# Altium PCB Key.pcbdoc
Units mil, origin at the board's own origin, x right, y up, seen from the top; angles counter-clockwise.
Board outline 1714.59 x 1483.35 mil, 2 copper layers (Top Layer, Bottom Layer); 3 components, 7 nets, 8 pads, 0 vias.
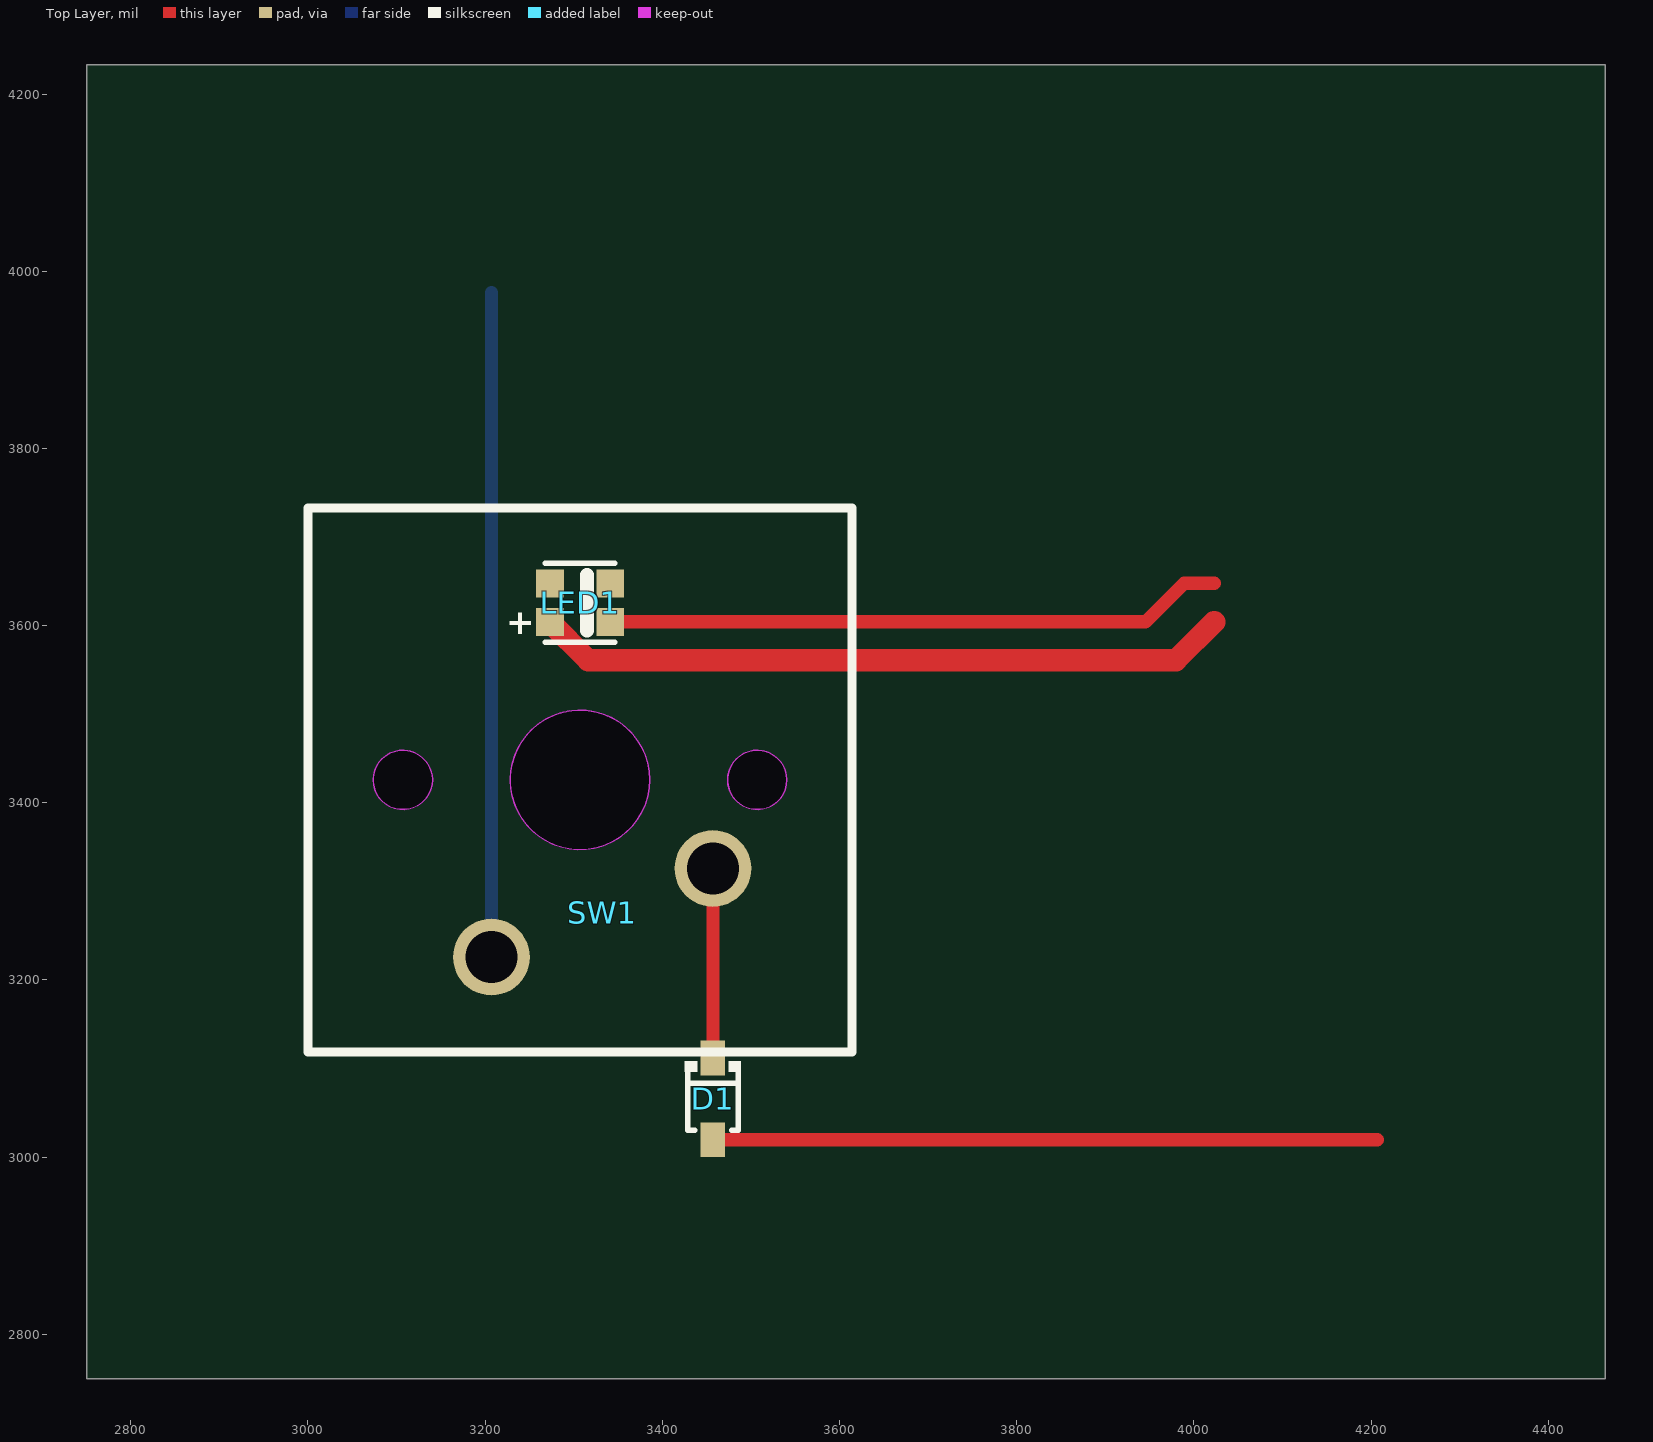
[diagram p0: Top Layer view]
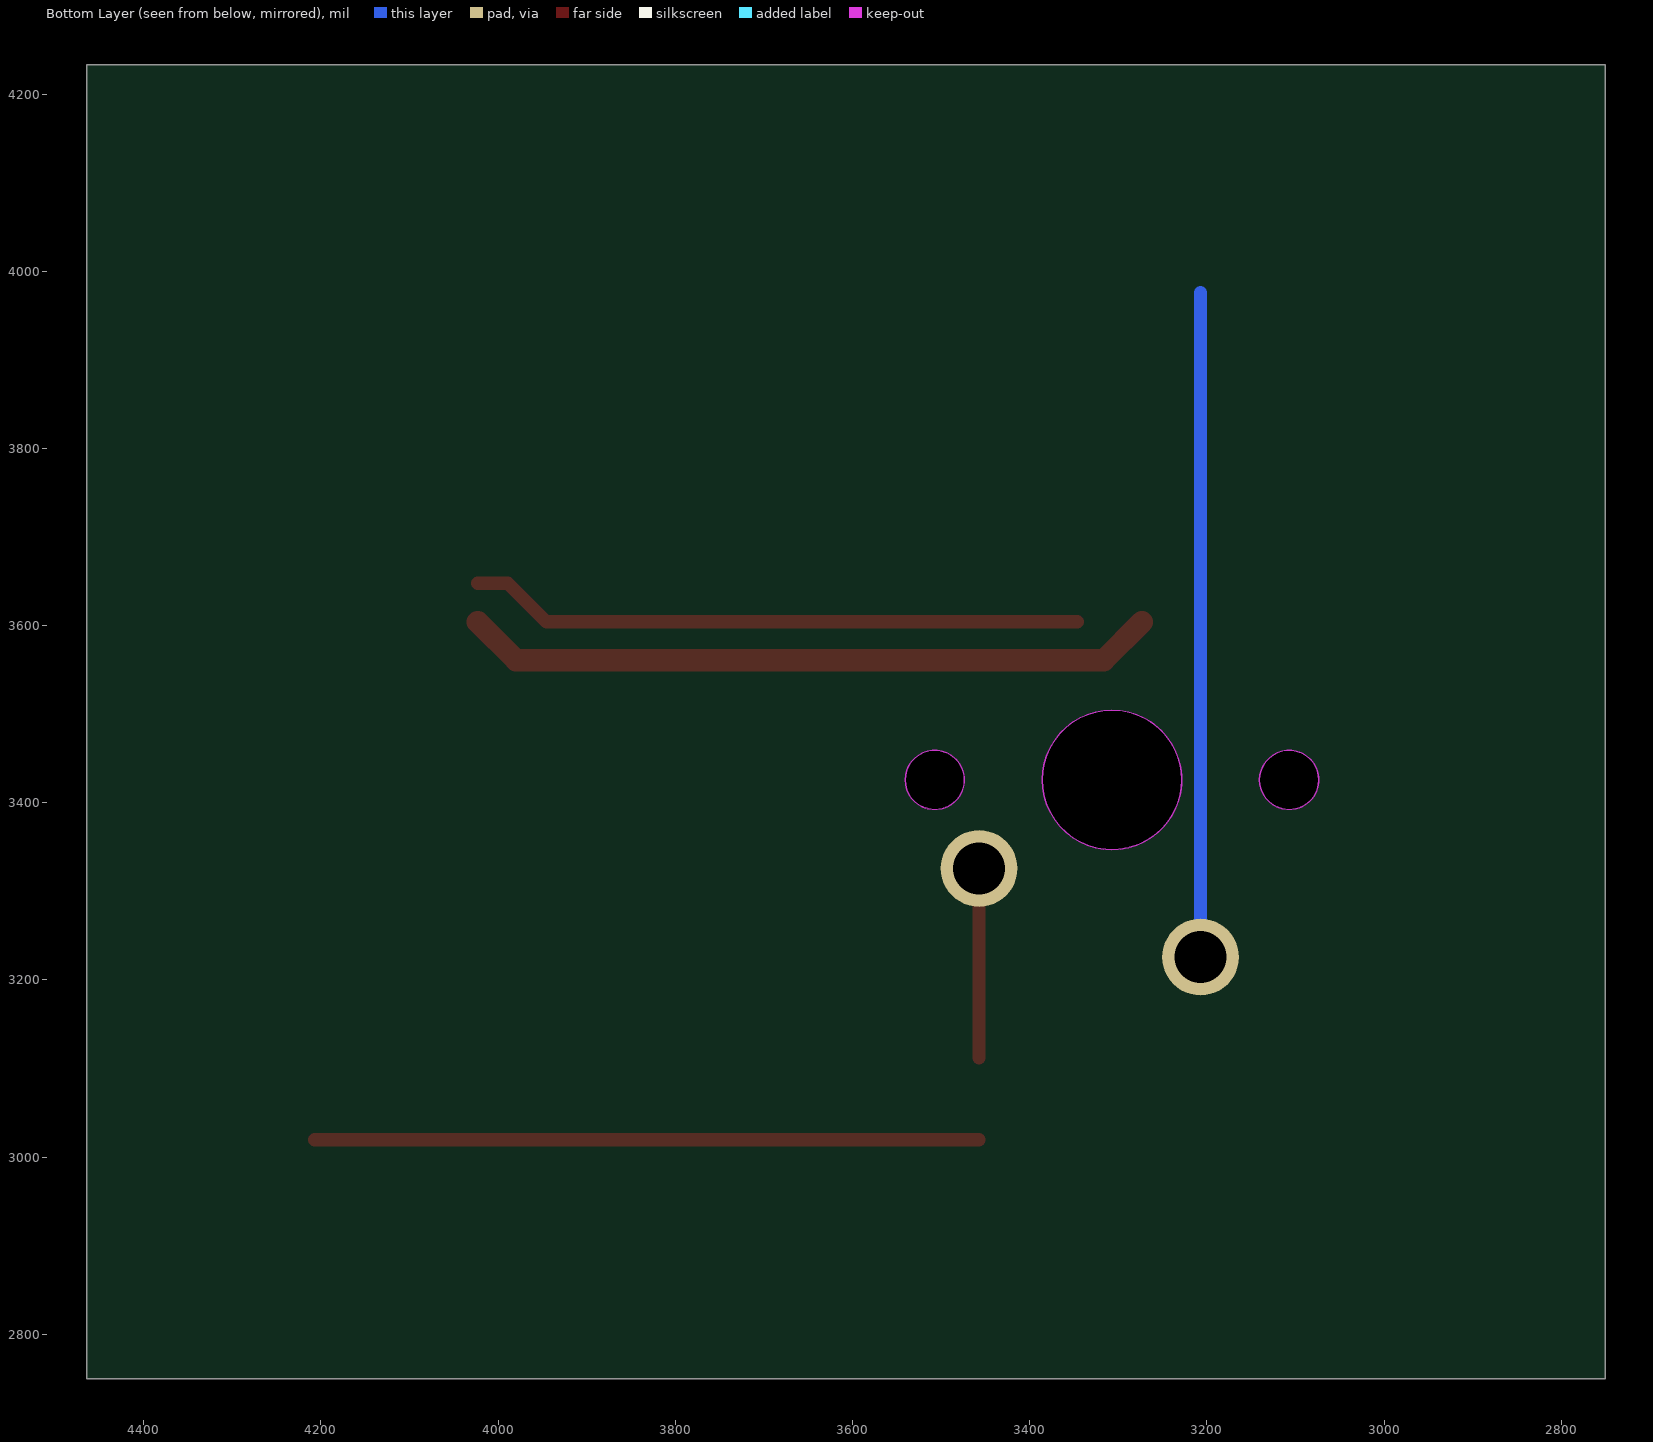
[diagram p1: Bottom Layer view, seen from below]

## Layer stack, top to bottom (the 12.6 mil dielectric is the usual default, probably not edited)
Top Layer: signal copper (thickness not stored)
Dielectric: dielectric 12.6, FR-4, Dk 4.8
Bottom Layer: signal copper (thickness not stored)

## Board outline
4464.59,2750 2750,2750 2750,4233.35 4464.59,4233.35

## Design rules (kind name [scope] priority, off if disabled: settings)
BoardOutlineClearance copperThickness1oz [All] p0: genericclearance=10 ignorepadtopadclearanceinfootprint=FALSE except(0: Arc-SplitContinuation Track-SplitContinuation SMDPad-SplitContinuation THPad-SplitContinuation Via-SplitContinuation Fill-SplitContinuation Poly-SplitContinuation Region-SplitContinuation Text-SplitContinuation; 6: Track-CutoutEdge SMDPad-CutoutEdge THPad-CutoutEdge Via-CutoutEdge Region-CutoutEdge; 11.8: Track-OutlineEdge SMDPad-OutlineEdge THPad-OutlineEdge Via-OutlineEdge Fill-OutlineEdge Region-OutlineEdge Poly-OutlineEdge Text-OutlineEdge Fill-CutoutEdge)
BoardOutlineClearance copperThickness2oz [All] p0: genericclearance=10 ignorepadtopadclearanceinfootprint=FALSE except(0: Arc-SplitContinuation Track-SplitContinuation SMDPad-SplitContinuation THPad-SplitContinuation Via-SplitContinuation Fill-SplitContinuation Poly-SplitContinuation Region-SplitContinuation Text-SplitContinuation; 6: Track-CutoutEdge SMDPad-CutoutEdge THPad-CutoutEdge Via-CutoutEdge Region-CutoutEdge; 11.8: Track-OutlineEdge SMDPad-OutlineEdge THPad-OutlineEdge Via-OutlineEdge Fill-OutlineEdge Region-OutlineEdge Poly-OutlineEdge Text-OutlineEdge Fill-CutoutEdge)
Clearance copperThickness1oz [(InNet('GND') OR InNet('VCC') OR InNet('COL') OR InNet('DI') OR InNet('DO') OR InNet('ROW') OR InNet('$1N2306'))] p1: gap=7 ignorepadtopadclearanceinfootprint=FALSE except(4: Track-Track; 6: Track-SMDPad SMDPad-SMDPad Track-THPad SMDPad-THPad THPad-THPad Track-Via SMDPad-Via THPad-Via Via-Via SMDPad-Fill THPad-Fill Via-Fill Fill-Fill Track-Region SMDPad-Region THPad-Region Via-Region Region-Region Track-Poly SMDPad-Poly THPad-Poly Via-Poly Fill-Poly Region-Poly Poly-Poly Track-Text SMDPad-Text THPad-Text Via-Text Fill-Text Region-Text Poly-Text Text-Text; 6.9: Track-Hole SMDPad-Hole THPad-Hole Via-Hole Fill-Hole Region-Hole Poly-Hole Text-Hole Sheet-Hole; 11.8: Track-Fill Fill-Region Track-Sheet SMDPad-Sheet THPad-Sheet Via-Sheet Fill-Sheet Region-Sheet Poly-Sheet Text-Sheet)
Clearance copperThickness2oz [All] p1: gap=7 ignorepadtopadclearanceinfootprint=FALSE except(6: Track-SMDPad SMDPad-SMDPad Track-THPad SMDPad-THPad THPad-THPad Track-Via SMDPad-Via THPad-Via Via-Via SMDPad-Fill THPad-Fill Via-Fill Fill-Fill Track-Region SMDPad-Region THPad-Region Via-Region Region-Region Track-Poly SMDPad-Poly THPad-Poly Via-Poly Fill-Poly Region-Poly Poly-Poly Track-Text SMDPad-Text THPad-Text Via-Text Fill-Text Region-Text Poly-Text Text-Text; 6.9: Track-Hole SMDPad-Hole THPad-Hole Via-Hole Fill-Hole Region-Hole Poly-Hole Text-Hole Sheet-Hole; 8: Track-Track; 11.8: Track-Fill Fill-Region Track-Sheet SMDPad-Sheet THPad-Sheet Via-Sheet Fill-Sheet Region-Sheet Poly-Sheet Text-Sheet)
DiffPairsRouting differentialPair [All] p1: maxuncoupledlength=10 minlimit=6 maxlimit=6 mostfreqgap=6 toplayer_minwidth=5 toplayer_prefwidth=10 toplayer_maxwidth=100 bottomlayer_minwidth=5 bottomlayer_prefwidth=10 bottomlayer_maxwidth=100
PasteMaskExpansion pasteMaskExpansion [All] p1: expansion=0
PlaneConnect innerPlane [All] p1: planeconnectstyle=Relief reliefexpansion=20 reliefentries=4 reliefconductorwidth=10 reliefairgap=10
PolygonConnect copperRegion [All] p1: connectstyle=Relief reliefentries=4 reliefconductorwidth=10 polygonreliefangle="90 Angle" airgapwidth=10
RoutingVias viaSize [All] p1: viastyle="Through Hole" holewidth=12.0078 minholewidth=11.811 maxholewidth=248.0314 width=24.0158 minwidth=19.685 maxwidth=393.7008
SolderMaskExpansion solderMaskExpansion [All] p1: useseparateexpansions=TRUE expansion=2 expansionbottom=2
Width copperThickness1oz [All] p1: maxlimit=100 minlimit=5 preferedwidth=10
Width copperThickness2oz [All] p1: maxlimit=100 minlimit=8 preferedwidth=10

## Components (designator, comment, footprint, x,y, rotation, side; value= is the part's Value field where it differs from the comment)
D1 "1N4148WS_C2128" SOD-323_L1.8-W1.3-LS2.5-RD 3457.09,3065.84 r270 top
LED1 "WS2812B-2020-V6" LED-SMD_4P-L2.2-W2.0-P1.00_WS2815C-2020-4P 3307.09,3625.86 r180 top
SW1 "MX1A-11NW" SW-TH_MX1A-11NW 3307.09,3425.84 r180 top

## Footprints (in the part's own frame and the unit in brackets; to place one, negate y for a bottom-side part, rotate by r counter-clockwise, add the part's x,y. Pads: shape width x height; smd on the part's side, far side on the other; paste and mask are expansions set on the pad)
LED-SMD_4P-L2.2-W2.0-P1.00_WS2815C-2020-4P [mm]
  rect 0.8x0.8 smd: 1(-0.865,0.55) 2(-0.865,-0.55) 3(0.865,-0.55) 4(0.865,0.55)
  silkscreen extent -1,-1.13 2.02,1.13
SOD-323_L1.8-W1.3-LS2.5-RD [mm]
  rect 1x0.7 smd: 1(-1.172,0) 2(1.172,0)
  silkscreen extent -1.08,-0.8 0.9,0.8
SW-TH_MX1A-11NW [mm]
  round 2.2 hole 1.5: 1(-3.81,2.54) 2(2.54,5.08)
  Board Outline Layer circle w0.025: c5.08,0 r0.851
  Board Outline Layer circle w0.025: c-5.08,0 r0.851
  Board Outline Layer circle w0.025: c0,0 r2
  Board Outline Layer region: 4.229,0 4.313,0.369 4.549,0.665 4.891,0.83 5.269,0.83 5.611,0.665 5.847,0.369 5.931,0 5.931,0 5.847,-0.369 5.611,-0.665 5.269,-0.83 4.891,-0.83 4.549,-0.665 4.313,-0.369 4.229,0
  Board Outline Layer region: -5.931,0 -5.847,0.369 -5.611,0.665 -5.269,0.83 -4.891,0.83 -4.549,0.665 -4.313,0.369 -4.229,0 -4.229,0 -4.313,-0.369 -4.549,-0.665 -4.891,-0.83 -5.269,-0.83 -5.611,-0.665 -5.847,-0.369 -5.931,0
  Board Outline Layer region: -2,0 -1.802,0.868 -1.247,1.564 -0.445,1.95 0.445,1.95 1.247,1.564 1.802,0.868 2,0 2,0 1.802,-0.868 1.247,-1.564 0.445,-1.95 -0.445,-1.95 -1.247,-1.564 -1.802,-0.868 -2,0
  Multi-Layer board cut-out: 4.229,0 4.313,0.369 4.549,0.665 4.891,0.83 5.269,0.83 5.611,0.665 5.847,0.369 5.931,0 5.931,0 5.847,-0.369 5.611,-0.665 5.269,-0.83 4.891,-0.83 4.549,-0.665 4.313,-0.369 4.229,0
  Multi-Layer board cut-out: -5.931,0 -5.847,0.369 -5.611,0.665 -5.269,0.83 -4.891,0.83 -4.549,0.665 -4.313,0.369 -4.229,0 -4.229,0 -4.313,-0.369 -4.549,-0.665 -4.891,-0.83 -5.269,-0.83 -5.611,-0.665 -5.847,-0.369 -5.931,0
  Multi-Layer board cut-out: -2,0 -1.802,0.868 -1.247,1.564 -0.445,1.95 0.445,1.95 1.247,1.564 1.802,0.868 2,0 2,0 1.802,-0.868 1.247,-1.564 0.445,-1.95 -0.445,-1.95 -1.247,-1.564 -1.802,-0.868 -2,0
  silkscreen extent -7.8,-7.8 7.8,7.8

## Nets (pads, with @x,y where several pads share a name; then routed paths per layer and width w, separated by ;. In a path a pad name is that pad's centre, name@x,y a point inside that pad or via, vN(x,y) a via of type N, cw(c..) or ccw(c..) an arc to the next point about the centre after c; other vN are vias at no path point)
$1N2306: D1.1 SW1.1 | length 213.8
  Top Layer w15: D1.1 SW1.1
COL: SW1.2 | length 750
  Bottom Layer w15: SW1.2 3207.09,3975.84
DI: LED1.3
DO: LED1.1 | length 694.9
  Top Layer w15: LED1.1@3346.14,3604.2 3945.39,3604.2 3988.95,3647.81 4022.99,3647.81
GND: LED1.2
ROW: D1.2 | length 750
  Top Layer w15: D1.2 4207.09,3019.68
VCC: LED1.4 | length 785.8
  Top Layer w25: LED1.4 3316.39,3560.84 3979.59,3560.84 4022.97,3604.2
